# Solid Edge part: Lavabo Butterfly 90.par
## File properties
Title: LAVABO BUTTERFLY 90 APP. O SOSP.
Author: DESYS
Template: Iso Part.par
Last saved by: PIM_1
Revision: 79
Application: Solid Edge
Tipo di contenuto documento: 0
Accuracy: 0,990
Document Number: 4005
Revision: 0
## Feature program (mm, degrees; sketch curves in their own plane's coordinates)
sketch for "unnamed Protrusion 1" plane through (10.8674, 0, 10.8674) normal (0, -1, 0) x-axis (1, 0, 0)
  line (-465.8674, 139.1326) -> (444.1326, 139.1326)
  line (444.1326, 139.1326) -> (444.1326, 99.1326)
  arc centre (468.4034, -116.0236) radius 216.5209 from (444.1326, 99.1326) to (279.1326, -10.8674) ccw
  line (279.1326, -10.8674) -> (-300.8674, -10.8674)
  arc centre (-490.1382, -116.0236) radius 216.5209 from (-300.8674, -10.8674) to (-465.8674, 99.1326) ccw
  line (-465.8674, 99.1326) -> (-465.8674, 139.1326)
  dimension (linear) = 465.8674
  dimension (linear) = 444.1326
  dimension (linear) = 279.1326
extrude "unnamed Protrusion 1" add finite 465 along -normal
sketch for "unnamed Cutout 1" plane through (-455, 230, 130) normal (-1, 0, 0) x-axis (0, 1, 0)
  arc centre (296.5104, 280.8333) radius 267.988 from (235, 20) to (75, 130) cw
extrude "unnamed Cutout 1" cut through
sketch for "ScavoEstrusione_3" plane through (0, 152.5, 0) normal (0, 0, -1) x-axis (-1, 0, 0)
extrude "ScavoEstrusione_3" cut finite 135 along -normal
sketch for "ScavoEstrusione_4" plane through (0, 152.5, 0) normal (0, 0, -1) x-axis (-1, 0, 0)
  line (-110, 137.5) -> (110, 137.5)
  arc centre (110, 97.5) radius 40 from (150, 97.5) to (110, 137.5) ccw
  line (150, -32.5) -> (150, 97.5)
  line (-150, -32.5) -> (150, -32.5)
  line (-150, -32.5) -> (-150, 97.5)
  arc centre (-110, 97.5) radius 40 from (-150, 97.5) to (-110, 137.5) cw
  dimension (linear) = 110
extrude "ScavoEstrusione_4" cut finite 25 along -normal
sketch for "ScavoEstrusione_6" plane through (0, 0, 75) normal (0, -1, 0) x-axis (-1, 0, 0)
extrude "ScavoEstrusione_6" cut finite 35 along -normal
fillet "Rotondo_3" radius 30
sketch for "ScavoEstrusione_8" #1 plane through (0, 152.5, 0) normal (0, 0, -1) x-axis (-1, 0, 0)
  line (270, 132.5) -> (208, 132.5)
  line (208, 132.5) -> (208, 70.5)
  line (208, 70.5) -> (270, 70.5)
  line (270, 70.5) -> (270, 132.5)
sketch for "ScavoEstrusione_8" #2 plane through (0, 152.5, 0) normal (0, 0, -1) x-axis (-1, 0, 0)
  line (-270, 132.5) -> (-208, 132.5)
  line (-208, 132.5) -> (-208, 70.5)
  line (-208, 70.5) -> (-270, 70.5)
  line (-270, 70.5) -> (-270, 132.5)
  dimension (linear) = 270
  dimension (linear) = 270
  dimension (linear) = 208
  dimension (linear) = 270
extrude "ScavoEstrusione_8" cut finite 30 along -normal
sketch for "ScavoEstrusione_11" #1 plane through (0, 0, 75) normal (0, -1, 0) x-axis (-1, 0, 0)
  circle centre (-415.2398, -55) radius 10
sketch for "ScavoEstrusione_11" #2 plane through (0, 0, 75) normal (0, -1, 0) x-axis (-1, 0, 0)
  circle centre (414.4169, -50) radius 10
extrude "ScavoEstrusione_11" cut finite 150 along -normal
sketch for "ScavoEstrusione_12" #1 plane through (0, 0, 75) normal (0, -1, 0) x-axis (-1, 0, 0)
  line (155, 5.2849) -> (165, 5.2849)
  arc centre (165, -7.2151) radius 12.5 from (165, 5.2849) to (165, -19.7151) cw
  line (165, -19.7151) -> (155, -19.7151)
  arc centre (155, -7.2151) radius 12.5 from (155, -19.7151) to (155, 5.2849) cw
sketch for "ScavoEstrusione_12" #2 plane through (0, 0, 75) normal (0, -1, 0) x-axis (-1, 0, 0)
  line (-165, -19.7151) -> (-155, -19.7151)
  arc centre (-155, -7.2151) radius 12.5 from (-155, -19.7151) to (-155, 5.2849) ccw
  line (-155, 5.2849) -> (-165, 5.2849)
  arc centre (-165, -7.2151) radius 12.5 from (-165, 5.2849) to (-165, -19.7151) ccw
extrude "ScavoEstrusione_12" cut finite 70 along -normal
sketch for "ProtrusioneEstrusa_2" plane through (0, 192.5, 25) normal (0, 0, -1) x-axis (-1, 0, 0)
extrude "ProtrusioneEstrusa_2" add finite 40 along +normal
sketch for "ScavoEstrusione_15" plane through (0, 230, 150) normal (0, 0, 1) x-axis (1, 0, 0)
extrude "ScavoEstrusione_15" cut finite 700 along -normal
sketch for "ScavoEstrusione_16" plane through (-3.2998, 202.5, -15) normal (0, 0, -1) x-axis (1, 0, 0)
  circle centre (3.2998, 2.5) radius 22.5
extrude "ScavoEstrusione_16" cut finite 525 along -normal
sketch for "ProtrusioneEstrusa_6" plane through (0, 230, 130) normal (-1, 0, 0) x-axis (0, 1, 0)
  line (-56.6511, 130) -> (-135, 130)
  line (-135, -13) -> (-135, 130)
  line (-135, -13) -> (-110, -13)
  line (-110, -13) -> (-110, 105)
  line (-110, 105) -> (-59.3301, 105)
  dimension (linear) = 135
extrude "ProtrusioneEstrusa_6" add finite 45 symmetric
sketch for "unnamed Protrusion 2" plane through (-3.2998, 95, 74) normal (0, -1, 0) x-axis (-1, 0, 0)
extrude "unnamed Protrusion 2" add through along -normal
fillet "Rotondo_5" radius 85
fillet "Rotondo_31" radius 150
fillet "Rotondo_7" radius 30
fillet "Rotondo_61" radius 45
fillet "Rotondo_13" radius 5
fillet "Rotondo_15" radius 10
fillet "Rotondo_19" radius 5
fillet "Rotondo_21" radius 5
fillet "Rotondo_25" radius 1
fillet "Rotondo_29" radius 5
fillet "Rotondo_28" radius 5
fillet "Rotondo_30" radius 20
fillet "Rotondo_26" radius 5
lofted cutout "unnamed LoftedCutout 1"
sketch for "unnamed Cutout 2" plane through (0, 130, 95) normal (0, 1, 0) x-axis (-1, 0, 0)
extrude "unnamed Cutout 2" cut to key point along -normal
sketch for "ScavoEstrusione_18" #1 plane through (0, 152.5, 0) normal (0, 0, -1) x-axis (-1, 0, 0)
sketch for "ScavoEstrusione_18" #2 plane through (0, 152.5, 0) normal (0, 0, -1) x-axis (-1, 0, 0)
  line (-270, 55.5) -> (-208, 55.5)
  line (-208, 55.5) -> (-208, -6.5)
  line (-208, -6.5) -> (-270, -6.5)
  line (-270, -6.5) -> (-270, 55.5)
  dimension (linear) = 270
  dimension (linear) = 270
  dimension (linear) = 208
  dimension (linear) = 270
extrude "ScavoEstrusione_18" cut finite 35 along -normal
fillet "Rotondo_33" radius 5
fillet "Rotondo_35" radius 10
chamfer "Smusso_1" setback 13
fillet "Rotondo_36" radius 5
fillet "Rotondo_39" radius 5
fillet "Rotondo_40" radius 3
fillet "Rotondo_41" radius 5
fillet "Rotondo_42" radius 5
fillet "Rotondo_45" radius 2
fillet "Rotondo_46" radius 2
fillet "Rotondo_54" radius 2
fillet "Rotondo_59" radius 30
fillet "Rotondo_58" radius 2
fillet "Rotondo_60" radius 2
fillet "Rotondo_63" radius 2
fillet "Rotondo_64" radius 2
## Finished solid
Body 1: solid body, 320 faces, 695 edges, 380 vertices.
  Faces by surface: cylinder 134, torus 81, plane 51, blend 35, sphere 16, cone 1, spline 1, swept 1
  Edges by curve: circle 357, line 246, intersection 81, ellipse 11
Bounding box of the edges (mm; curved faces can reach further): 910.000 x 465.000 x 165.000, from (-455, 0, -15) to (455, 465, 150).
Cylindrical faces by radius (mm): R2 x20, R3 x23, R5 x50, R10 x10, R12.5 x5, R17.5 x1, R20 x1, R22.5 x1, R30 x10, R32.5 x1, R40 x2, R45 x2, R60 x1, R70 x2, R150 x2, R216.5209 x2, R267.988 x1
Conical faces (half-angle, radius in mm at the cone's reference point): 45 deg R35.5 x1
Toroidal faces (ring radius, tube radius in mm): R3 r2 x8, R8 r3 x16, R10 r5 x1, R12 r2 x2, R14.5 r2 x9, R15 r5 x1, R22.5 r5 x2, R24.5 r2 x1, R25 r5 x5, R27.5 r5 x1, R28 r2 x8, R31.5 r1 x1, R33 r3 x2, R35 r5 x4, R37.5 r5 x1, R37.5711 r5 x1, R40 r5 x2, R43 r3 x2, R55 r5 x1, R65 r5 x3, R73 r3 x2, R147 r3 x2, R155 r5 x4, R221.5209 r5 x2
Spherical faces by radius (mm): R5 x12, R10 x4
Planar faces by outward normal: +x 8, +y 8, +z 4, -x 8, -y 11, -z 10, oblique 2
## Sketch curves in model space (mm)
line (325, 130, 150) -> (-325, 130, 150)
line (-325, 130, 150) -> (-325, 425, 150)
arc centre (0, 10994.1378, 150) radius 10574.1335 from (325, 425, 150) through (0, 420.0043, 150) to (-325, 425, 150)
line (325, 425, 150) -> (325, 130, 150)
line (290, 130, 40) -> (-290, 130, 40)
line (-290, 130, 40) -> (-290, 250, 40)
line (-290, 250, 40) -> (290, 250, 40)
line (290, 250, 40) -> (290, 130, 40)
arc centre (0, 465, -20590) radius 20705 from (455, 465, 110) through (0, 465, 115) to (-455, 465, 110)
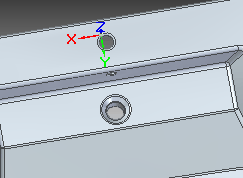
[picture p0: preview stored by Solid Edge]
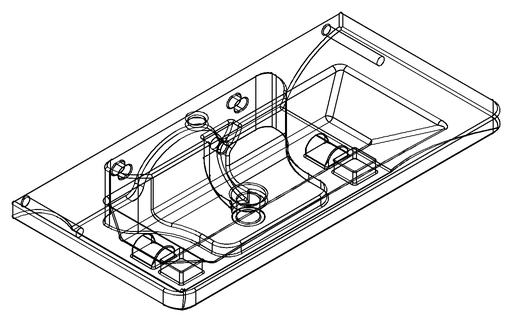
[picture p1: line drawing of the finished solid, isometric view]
